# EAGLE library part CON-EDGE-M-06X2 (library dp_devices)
Male 6x2 PCB Edge connector
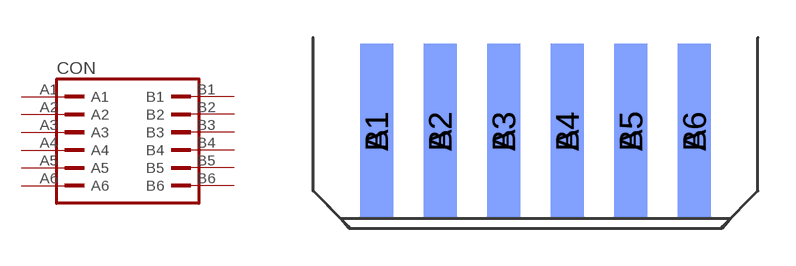
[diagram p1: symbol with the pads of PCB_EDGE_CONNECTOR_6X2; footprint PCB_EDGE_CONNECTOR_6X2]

Designator prefix CON

## CON-EDGE-M-06X2  [PCB_EDGE_CONNECTOR_6X2]
A1  A1  pas
A2  A2  pas
A3  A3  pas
A4  A4  pas
A5  A5  pas
A6  A6  pas
B1  B1  pas
B2  B2  pas
B3  B3  pas
B4  B4  pas
B5  B5  pas
B6  B6  pas

## Footprint PCB_EDGE_CONNECTOR_6X2 (pad centres in mm)
smd 1.32 x 7: A1 -6.35,2.603; A2 -3.81,2.603; A3 -1.27,2.603; A4 1.27,2.603; A5 3.81,2.603; A6 6.35,2.603
smd 1.32 x 7 bottom: B1 -6.35,2.603; B2 -3.81,2.603; B3 -1.27,2.603; B4 1.27,2.603; B5 3.81,2.603; B6 6.35,2.603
